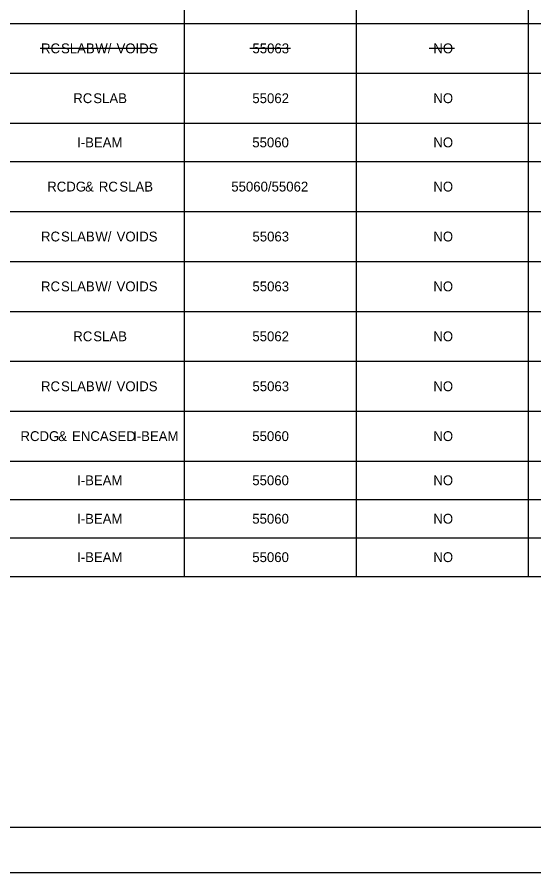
# Model space of a CAD drawing. Extents: x 18 to 14744716, y -5 to 1829144.
# Drawn here: x 32.59 to 39.14, y -5.37 to 5.47 of the extents above; entities that cross this region are included whole.
import ezdxf

# ---------------------------------------------------------------- set-up
doc = ezdxf.new("R2010")
doc.units = 0
for name, color, linetype in [('B_Dimensions', 7, 'Continuous'), ('B_Text', 7, 'Continuous'), ('R_Border', 7, 'Continuous'), ('R_No Plot', 7, 'Continuous')]:
    doc.layers.add(name, color=color, linetype=linetype)

msp = doc.modelspace()

# ---------------------------------------------------------------- linework, layer by layer
at = {"layer": 'B_Dimensions'}
for p, q in [((32.881, 5.079), (34.368, 5.079)), ((35.538, 5.079), (36.055, 5.079)), ((37.812, 5.079), (38.133, 5.079))]:
    msp.add_line(p, q, dxfattribs=at)
at = {"layer": 'B_Text'}
for p, q in [((34.711, -1.614), (34.711, 14.85)), ((36.889, -1.614), (36.889, 14.85)), ((39.067, -1.614), (39.067, 14.85)), ((24.356, 5.395), (47.013, 5.395)), ((23.2, 4.762), (47.013, 4.762)), ((24.356, 4.13), (47.013, 4.13)), ((23.2, 3.643), (47.013, 3.643)), ((23.2, 3.01), (47.013, 3.01)), ((24.356, 2.377), (47.013, 2.377)), ((24.356, 1.745), (47.013, 1.745)), ((23.2, 1.112), (47.013, 1.112)), ((24.356, 0.479), (47.013, 0.479)), ((23.2, -0.153), (47.013, -0.153)), ((24.356, -0.64), (47.013, -0.64)), ((24.356, -1.127), (47.013, -1.127)), ((23.2, -1.614), (47.013, -1.614))]:
    msp.add_line(p, q, dxfattribs=at)
at = {"layer": 'R_Border'}
msp.add_line((51.2, -4.796), (19.293, -4.796), dxfattribs=at)
at = {"layer": 'R_No Plot'}
msp.add_lwpolyline([(17.777, 16.628), (51.777, 16.628), (51.777, -5.372), (17.777, -5.372)], close=True, dxfattribs=at)

# ---------------------------------------------------------------- texts
at = {"layer": 'B_Text'}
for s, p in [('RC', (32.892, 5.016)), (' SLAB', (33.099, 5.016)), (' W/', (33.534, 5.016)), (' VOIDS', (33.803, 5.016)), ('55063', (35.571, 5.016)), ('NO', (37.863, 5.016)), ('RC', (33.301, 4.384)), (' SLAB', (33.508, 4.384)), ('55062', (35.57, 4.384)), ('NO', (37.863, 4.384)), ('I-BEAM', (33.349, 3.824)), ('55060', (35.569, 3.824)), ('NO', (37.863, 3.824)), ('RCDG', (32.971, 3.264)), (' &', (33.403, 3.264)), (' RC', (33.578, 3.264)), (' SLAB', (33.838, 3.264)), ('55060/55062', (35.303, 3.264)), ('NO', (37.863, 3.264)), ('RC', (32.892, 2.631)), (' SLAB', (33.099, 2.631)), (' W/', (33.534, 2.631)), (' VOIDS', (33.803, 2.631)), ('55063', (35.571, 2.631)), ('NO', (37.863, 2.631)), ('RC', (32.892, 1.999)), (' SLAB', (33.099, 1.999)), (' W/', (33.534, 1.999)), (' VOIDS', (33.803, 1.999)), ('55063', (35.571, 1.999)), ('NO', (37.863, 1.999)), ('RC', (33.301, 1.366)), (' SLAB', (33.508, 1.366)), ('55062', (35.57, 1.366)), ('NO', (37.863, 1.366)), ('RC', (32.892, 0.733)), (' SLAB', (33.099, 0.733)), (' W/', (33.534, 0.733)), (' VOIDS', (33.803, 0.733)), ('55063', (35.571, 0.733)), ('NO', (37.863, 0.733)), ('RCDG', (32.632, 0.101)), (' &', (33.064, 0.101)), (' ENCASED', (33.239, 0.101)), (' I-BEAM', (34.012, 0.101)), ('55060', (35.569, 0.101)), ('NO', (37.863, 0.101)), ('I-BEAM', (33.349, -0.459)), ('55060', (35.569, -0.459)), ('NO', (37.863, -0.459)), ('I-BEAM', (33.349, -0.946)), ('55060', (35.569, -0.946)), ('NO', (37.863, -0.946)), ('I-BEAM', (33.349, -1.433)), ('55060', (35.569, -1.433)), ('NO', (37.863, -1.433))]:
    msp.add_text(s, height=0.1248, dxfattribs=at).set_placement(p)

doc.saveas('drawing.dxf')
